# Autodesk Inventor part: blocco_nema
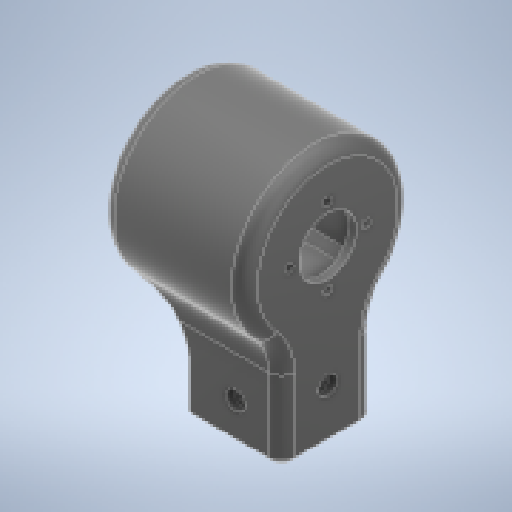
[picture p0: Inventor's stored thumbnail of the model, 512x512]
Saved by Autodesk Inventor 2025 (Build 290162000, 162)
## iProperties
Created: 2026-03
Part Number: blocco_nema
Material: Plastica ABS
Document SubType Name: Modeling
Designer: R5800u
Density: 1.06 g/cm^3
Appearance: Liscia - Nero
Author: R5800u
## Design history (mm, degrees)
sketch "Schizzo1"
  geometry: L1 (18, 18)-(-18, 18); L2 (-18, 18)-(-18, -18); L3 (-18, -18)-(18, -18); L4 (18, -18)-(18, 18); L5 (18, 18)-(-18, -18); L6 (-18, 18)-(18, -18); L7 (10, 10)-(-10, 10); L8 (-10, 10)-(-10, -10); L9 (-10, -10)-(10, -10); L10 (10, -10)-(10, 10); L11 (10, 10)-(-10, -10); L12 (-10, 10)-(10, -10); 1 further point
  constraints: 24 end point, 4 midpoint, 4 parallel, 2 horizontal, 2 perpendicular
  dimensions: "d0" = 36 distance of L3.end L2.end; "d1" = 36 distance of L2.end L1.end; "d2" = 20 distance of L9.end L8.end; "d3" = 20 distance of L8.end L7.end
extrude "Estrusione1" new body sketch "Schizzo1" distance "d4" = 40; taper "d5" = 0 deg
sketch "Schizzo2" dims "d6" = 65
  geometry: L1 (40, -18)-(40, 18) reference; L2 (40, 0)-(87.596, 0); L3 (88.06, 21)-(46.06, 21); L4 (46.06, 21)-(46.06, -21); L5 (46.06, -21)-(88.06, -21); L6 (88.06, -21)-(88.06, 21); L7 (88.06, 21)-(46.06, -21); L8 (46.06, 21)-(88.06, -21); 3 further points
  constraints: 14 end point, 3 midpoint, 2 horizontal, 2 parallel, 1 perpendicular, 1 point on line, 3 other
  dimensions: "d7" = 42 distance of L5.end L4.end; "d8" = 42 distance of L4.end L3.end
extrude "Estrusione2" join sketch "Schizzo2" stored distance "d9" = 36; taper "d10" = 0 deg
sketch "Schizzo3"
  geometry: L1 (-3, 88.06)-(39, 88.06) reference; L2 (39, 88.06)-(39, 46.06) reference; L3 (39, 46.06)-(-3, 46.06) reference; L4 (-3, 46.06)-(-3, 88.06) reference; L5 (0, 0)-(36, 0) reference; L6 (36, 0)-(36, 40) reference; L7 (0, 0)-(0, 40) reference; A1 r 32.5 centre (18, 67.06) between (36, 40) and (0, 40) reference; 3 further points
  constraints: 1 coincident, 3 other
extrude "Estrusione3" join sketch "Schizzo3" distance "d11" = 20; taper "d12" = 0 deg
fillet "Raccordo1" dims "d13" = 20
sketch "Schizzo4"
  geometry: L1 (-3, 88.06)-(39, 88.06) reference; L2 (39, 88.06)-(39, 46.06) reference; L3 (39, 46.06)-(-3, 46.06) reference; L4 (-3, 46.06)-(-3, 88.06) reference; L5 (0, 0)-(36, 0) reference; L6 (36, 0)-(36, 30.835) reference; L7 (0, 0)-(0, 30.835) reference; C1 r 11.25 at (18, 67.06); C2 r 1.621 at (18, 82.06) reference; C3 r 1.621 at (3, 67.06) reference; C4 r 1.621 at (18, 52.06) reference; C5 r 1.621 at (33, 67.06) reference; A1 r 20 centre (56, 30.835) between (41.524, 44.635) and (36, 30.835) reference; A2 r 32.5 centre (18, 67.06) between (41.524, 44.635) and (-5.524, 44.635) reference; A3 r 20 centre (-20, 30.835) between (0, 30.835) and (-5.524, 44.635) reference; 1 further point
  constraints: 1 centre point, 1 coincident
  dimensions: "d14" = 22.5 diameter of C1
  node "Linea chiusa proiettata2"
  node "Riferimento1"
  node "Riferimento2"
  node "Riferimento3"
  node "Riferimento4"
node "Piano di lavoro1"
extrude "Estrusione4" join sketch "Schizzo4" stored distance "d15" = 20; taper "d16" = 0 deg
fillet "Raccordo2" dims "d17" = 5
chamfer "Smusso3" distance "d24" = 3; stored, may be unused: second distance "d25" = 2, angle "d26" = 45 deg
fillet "Raccordo3" dims "d27" = 4
sketch "Schizzo5"
  geometry: L1 (22.037, -30.835)-(22.037, -15.835)
  constraints: 2 end point, 1 vertical
  dimensions: "d28" = 15 distance of L1.start L1.end
hole "Foro1" sketch "Schizzo5" at (22.037, -15.835) diameter "d29" = 4.3; stored, may be unused: countersink angle "d33" = 90 deg, drill point angle "d35" = 118 deg; dims "d30" = 6, "d31" = 7.5, "d32" = 3, "d34" = 8
sketch "Schizzo6"
  geometry: C1 r 2.15 at (13, -15.835) reference; 2 further points
  constraints: 1 coincident
hole "Foro2" sketch "Schizzo6" at (13, -15.835) diameter "d36" = 4.3; stored, may be unused: countersink angle "d40" = 90 deg, drill point angle "d42" = 118 deg; dims "d37" = 6, "d38" = 7.5, "d39" = 3, "d41" = 8
sketch "Schizzo7"
  geometry: L1 (0, -67.06)-(0, -47.06)
  constraints: 2 end point, 1 vertical
  dimensions: "d43" = 20 distance of L1.start L1.end
hole "Foro3" sketch "Schizzo7" at (0, -47.06) diameter "d44" = 4.3; stored, may be unused: countersink angle "d48" = 90 deg, drill point angle "d50" = 118 deg; dims "d45" = 6, "d46" = 7.5, "d47" = 3, "d49" = 8
chamfer "Smusso4" distance "d51" = 2; stored, may be unused: second distance "d52" = 2, angle "d53" = 45 deg
node "Solido1"
node "Linea chiusa proiettata1"
